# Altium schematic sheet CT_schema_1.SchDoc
size 546 x 556 mm
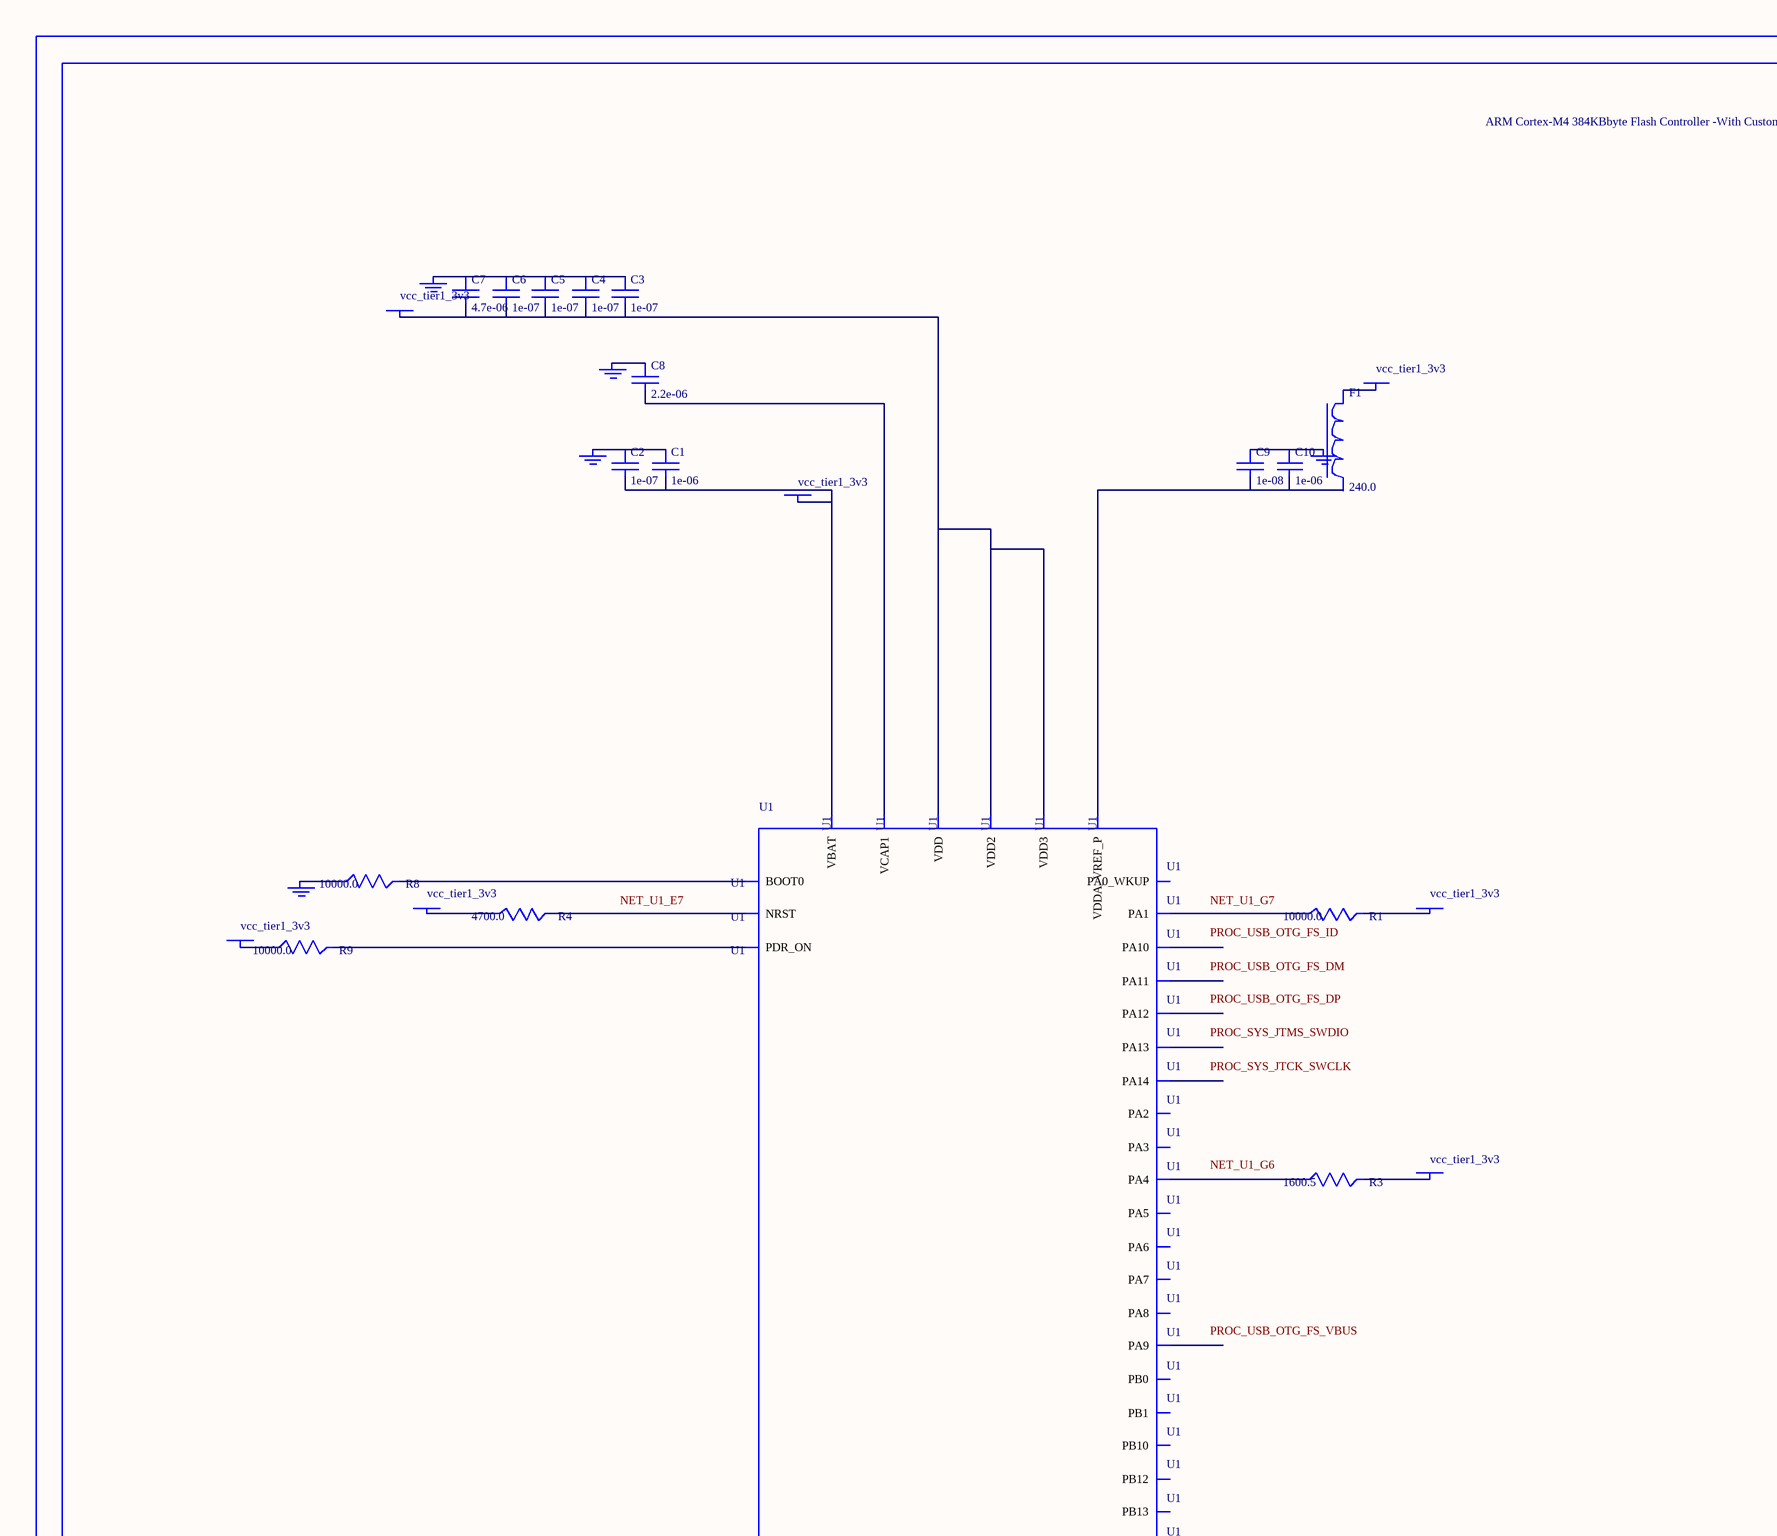
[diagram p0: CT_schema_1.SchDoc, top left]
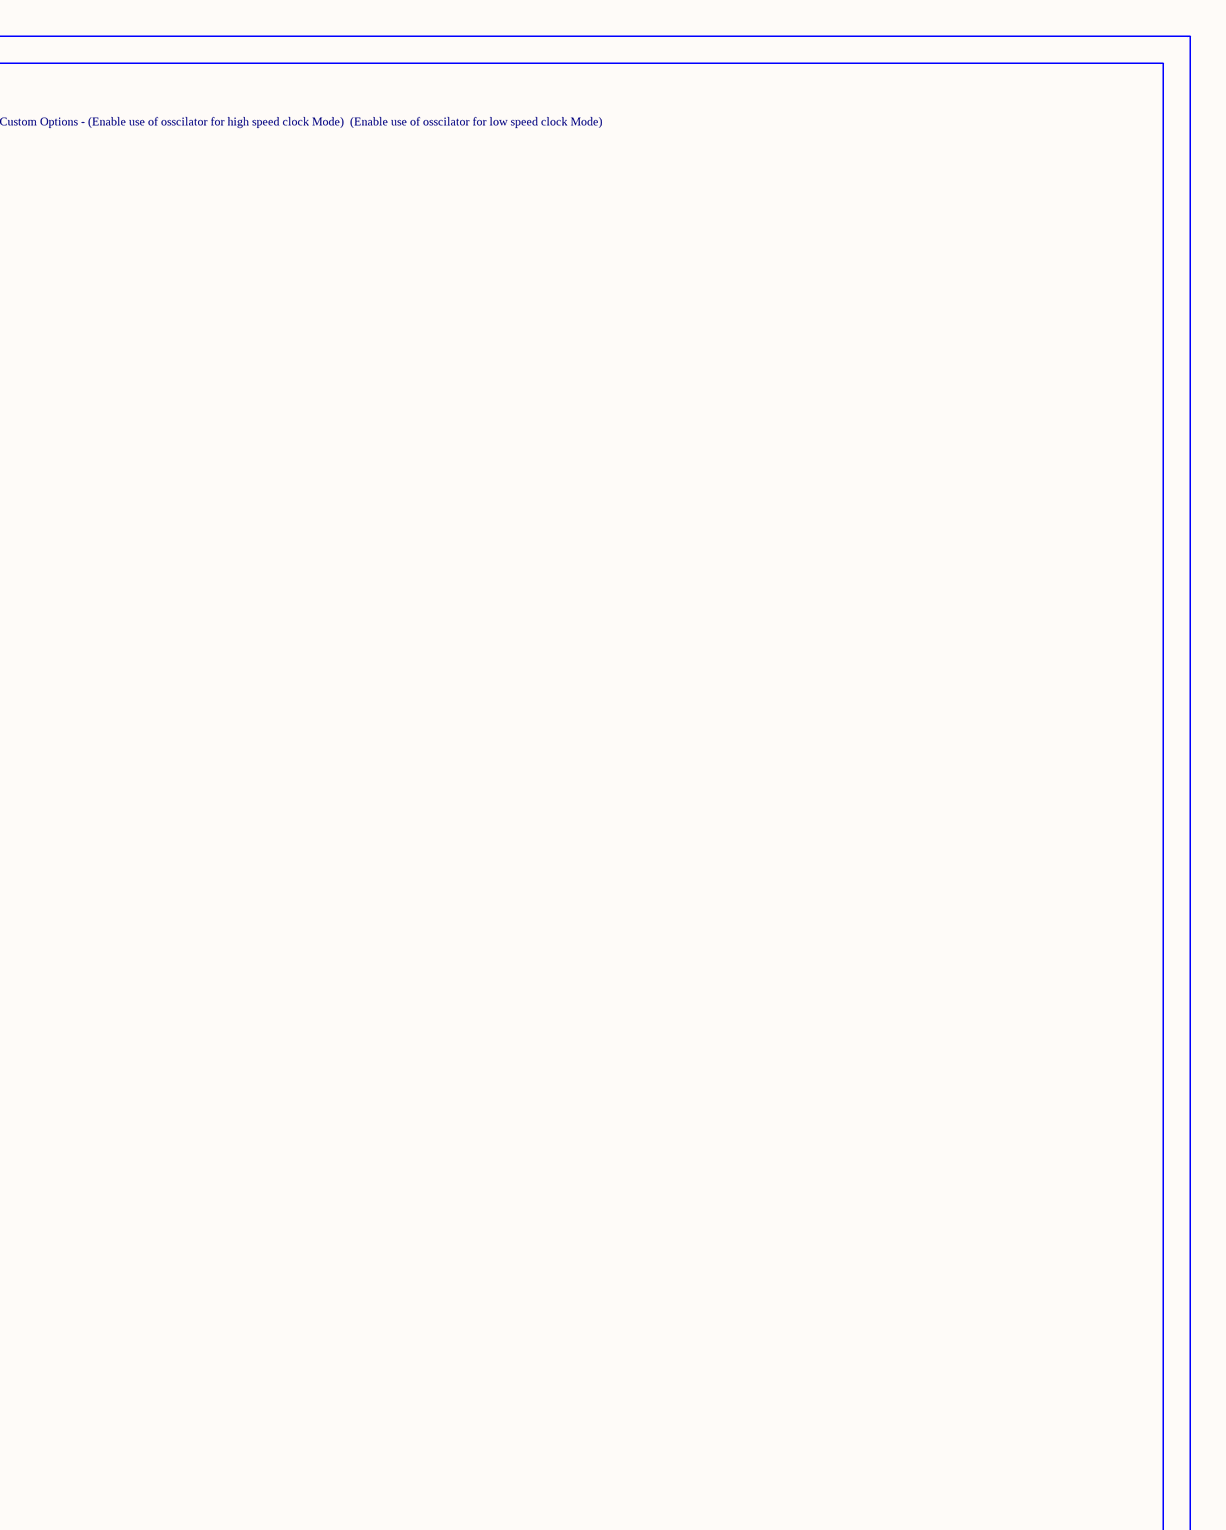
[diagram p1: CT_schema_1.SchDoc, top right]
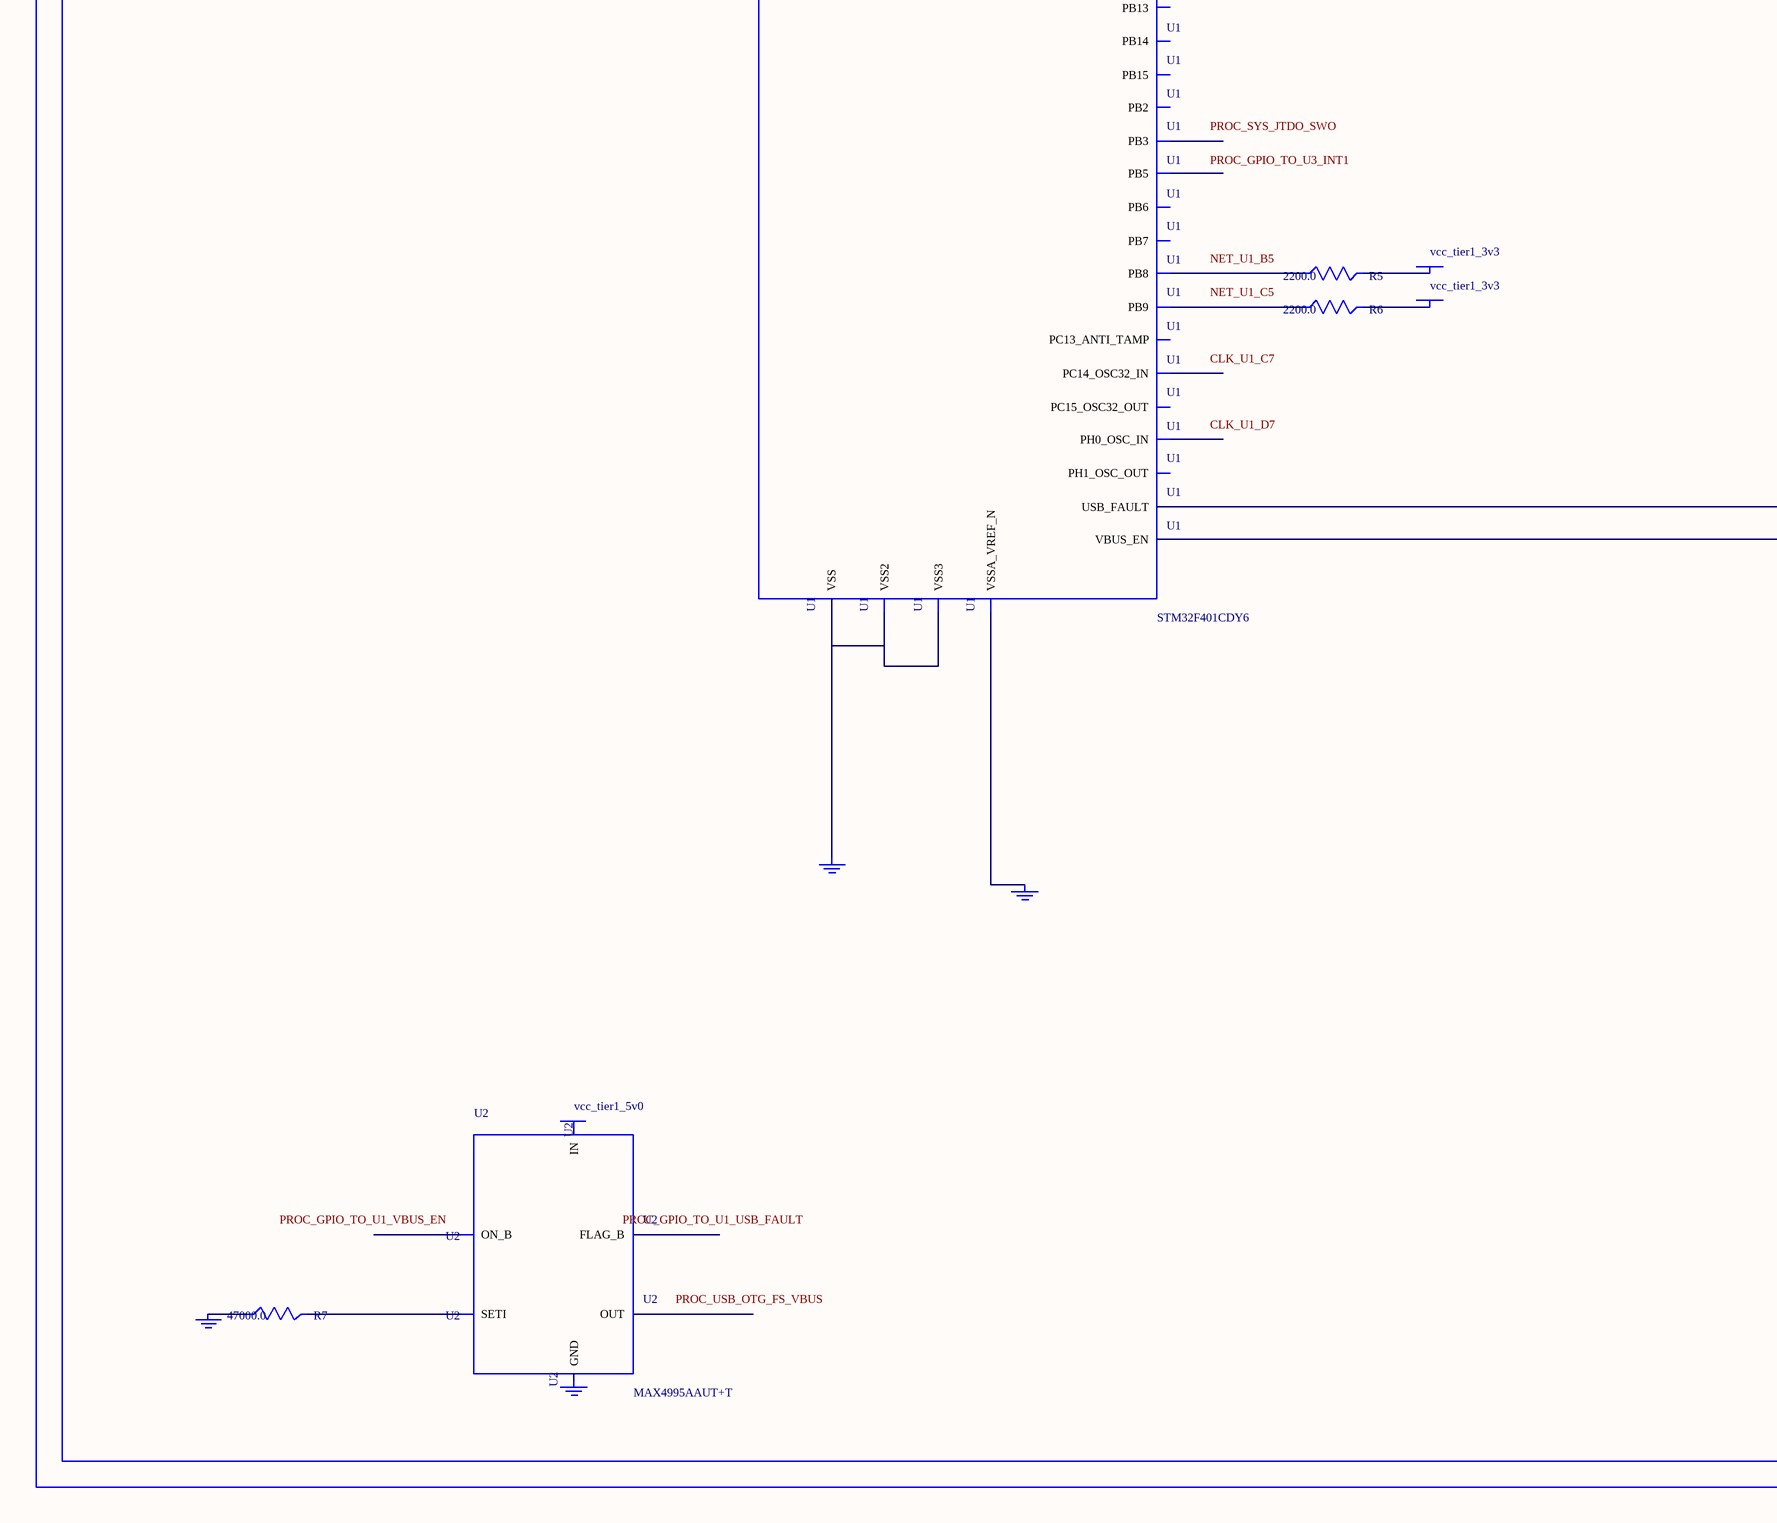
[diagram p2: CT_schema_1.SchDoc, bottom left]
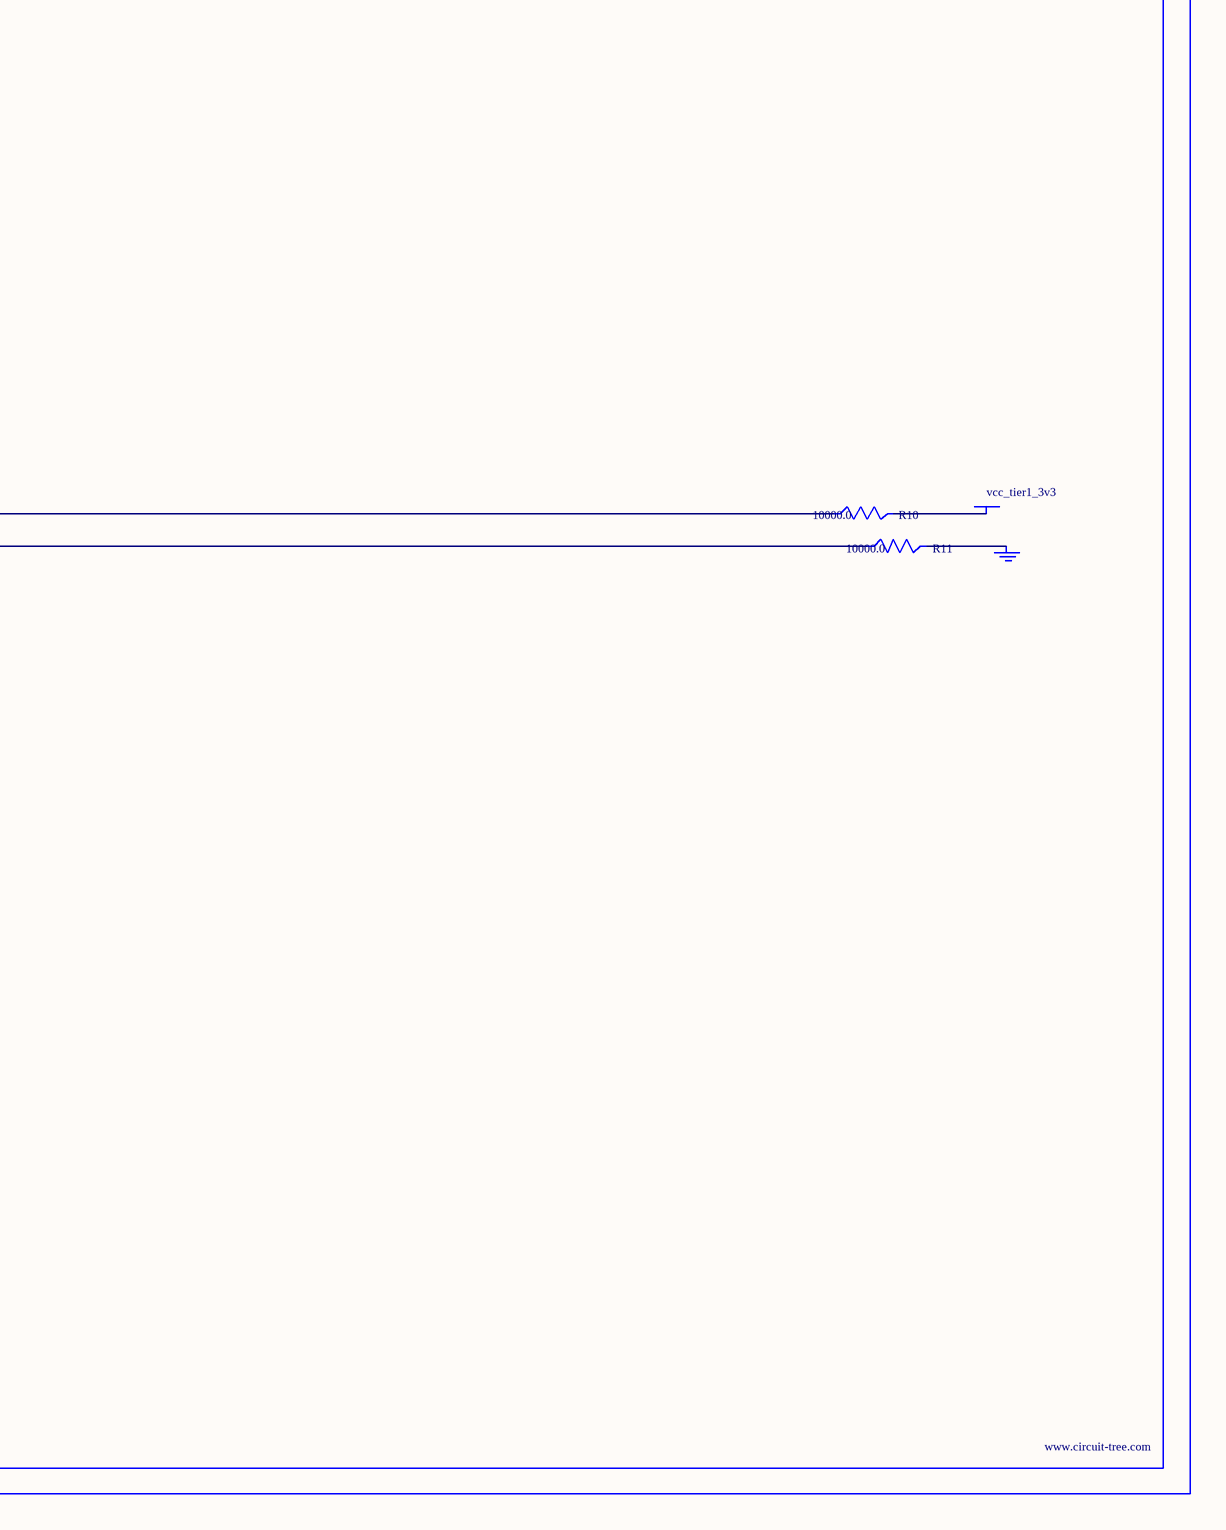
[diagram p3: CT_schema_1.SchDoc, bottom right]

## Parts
BORDER0  (no value)
C1  1e-06  [C0603]
C2  1e-07  [C0603]
C3  1e-07  [C0603]
C4  1e-07  [C0603]
C5  1e-07  [C0603]
C6  1e-07  [C0603]
C7  4.7e-06  [C0603]
C8  2.2e-06  [C0603]
C9  1e-08  [C0603]
C10  1e-06  [C0603]
F1  240.0  [L0603]
GND_INSTANCE_0_0  (no value)
GND_INSTANCE_0_1  (no value)
GND_INSTANCE_0_2  (no value)
GND_INSTANCE_0_3  (no value)
GND_INSTANCE_0_4  (no value)
GND_INSTANCE_0_5  (no value)
GND_INSTANCE_0_6  (no value)
GND_INSTANCE_0_7  (no value)
GND_INSTANCE_0_8  (no value)
GND_INSTANCE_0_9  (no value)
POWER_INSTANCE_0_0  vcc_tier1_3v3
POWER_INSTANCE_0_1  vcc_tier1_3v3
POWER_INSTANCE_0_2  vcc_tier1_3v3
POWER_INSTANCE_0_3  vcc_tier1_3v3
POWER_INSTANCE_0_4  vcc_tier1_3v3
POWER_INSTANCE_0_5  vcc_tier1_3v3
POWER_INSTANCE_0_6  vcc_tier1_3v3
POWER_INSTANCE_0_7  vcc_tier1_3v3
POWER_INSTANCE_0_8  vcc_tier1_3v3
POWER_INSTANCE_0_9  vcc_tier1_3v3
POWER_INSTANCE_0_10  vcc_tier1_5v0
R1  10000.0  [R0603]
R3  1600.5  [R0603]
R4  4700.0  [R0603]
R5  2200.0  [R0603]
R6  2200.0  [R0603]
R7  47000.0  [R0603]
R8  10000.0  [R0603]
R9  10000.0  [R0603]
R10  10000.0  [R0603]
R11  10000.0  [R0603]
U1  STM32F401CDY6  [WLCSP49]
U2  MAX4995AAUT+T  [SOT-23-6]

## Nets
NetC1_1: C1.1 C2.1 GND_INSTANCE_0_0.0(GND)
NetC1_2: C1.2 C2.2 POWER_INSTANCE_0_0.0(PWR) U1.B7(VBAT)
NetC3_1: C3.1 C4.1 C5.1 C6.1 C7.1 GND_INSTANCE_0_2.0(GND)
NetC3_2: C3.2 C4.2 C5.2 C6.2 C7.2 POWER_INSTANCE_0_2.0(PWR) U1.A7(VDD) U1.B2(VDD2) U1.F2(VDD3)
NetC8_1: C8.1 GND_INSTANCE_0_4.0(GND)
NetC8_2: C8.2 U1.G2(VCAP1)
NetC9_1: C9.1 C10.1 GND_INSTANCE_0_1.0(GND)
NetC9_2: C9.2 C10.2 U1.F7(VDDA_VREF_P)
NetF1_1: F1.1 POWER_INSTANCE_0_1.0(PWR)
NetGND_INSTANCE_0_3_0: GND_INSTANCE_0_3.0(GND) R8.1
NetGND_INSTANCE_0_5_0: GND_INSTANCE_0_5.0(GND) R11.2
NetGND_INSTANCE_0_6_0: GND_INSTANCE_0_6.0(GND) U1.E6(VSSA_VREF_N)
NetGND_INSTANCE_0_7_0: GND_INSTANCE_0_7.0(GND) U1.A6(VSS) U1.B1(VSS2) U1.D3(VSS3)
NetGND_INSTANCE_0_8_0: GND_INSTANCE_0_8.0(GND) R7.1
NetPOWER_INSTANCE_0_3_0: POWER_INSTANCE_0_3.0(PWR) R9.1
NetPOWER_INSTANCE_0_4_0: POWER_INSTANCE_0_4.0(PWR) R10.2
NetPOWER_INSTANCE_0_5_0: POWER_INSTANCE_0_5.0(PWR) R4.1
NetPOWER_INSTANCE_0_6_0: POWER_INSTANCE_0_6.0(PWR) R1.2
NetPOWER_INSTANCE_0_7_0: POWER_INSTANCE_0_7.0(PWR) R3.2
NetPOWER_INSTANCE_0_8_0: POWER_INSTANCE_0_8.0(PWR) R5.2
NetPOWER_INSTANCE_0_9_0: POWER_INSTANCE_0_9.0(PWR) R6.2
NetR1_1: R1.1 U1.G7(PA1)
NetR3_1: R3.1 U1.G6(PA4)
NetR4_2: R4.2 U1.E7(NRST)
NetR5_1: R5.1 U1.B5(PB8)
NetR6_1: R6.1 U1.C5(PB9)
NetR7_2: R7.2 U2.3(SETI)
NetR8_2: R8.2 U1.A5(BOOT0)
NetR9_2: R9.2 U1.B6(PDR_ON)
NetR10_1: R10.1 U1.A4(USB_FAULT)
NetR11_1: R11.1 U1.A2(VBUS_EN)

Not connected (* = marked no-connect by the designer): F1 2; GND_INSTANCE_0_9 0(GND); POWER_INSTANCE_0_10 0(PWR); U1 A1(PA14) A3(PB3) B3(PA13) B4(PB5) C1(PA11) C2(PA10) C3(PA12) C4(PB6) C6(PC15_OSC32_OUT) C7(PC14_OSC32_IN) D1(PA8) D2(PA9) D4(PB7) D5(PC13_ANTI_TAMP) D6(PH1_OSC_OUT) D7(PH0_OSC_IN) E1(PB15) E2(PB12) E3(PB10) E4(PA3) E5(PA2) F1(PB14) F3(PA7) F4(PA6) F5(PA5) F6(PA0_WKUP) G1(PB13) G3(PB2) G4(PB1) G5(PB0); U2 1(OUT) 2(GND) 4(ON_B) 5(IN) 6(FLAG_B)

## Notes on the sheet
- Labels drawn without touching a wire or pin: CLK_U1_C7, CLK_U1_D7, NET_U1_B5, NET_U1_C5, NET_U1_E7, NET_U1_G6, NET_U1_G7, PROC_GPIO_TO_U1_USB_FAULT, PROC_GPIO_TO_U1_VBUS_EN, PROC_GPIO_TO_U3_INT1, PROC_SYS_JTCK_SWCLK, PROC_SYS_JTDO_SWO, PROC_SYS_JTMS_SWDIO, PROC_USB_OTG_FS_DM, PROC_USB_OTG_FS_DP, PROC_USB_OTG_FS_ID, PROC_USB_OTG_FS_VBUS

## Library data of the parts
BORDER0 = BORDER_PAGE0
C1 C10 = C0603C105K3RACTU
C2-C6 = 06035C104K4Z2A
C7 = GRM188R6YA475KE15D
C8 = C0603C225K8RACTU
C9 = 06035C103K4Z2A
F1 = Z0603C241ASMST
GND_INSTANCE_0_0-GND_INSTANCE_0_9 = GND
POWER_INSTANCE_0_0-POWER_INSTANCE_0_10 = PWR
R1 R8-R11 = RC0603JR-0710KL
R3 = R3
R4 = RC0603JR-074K7L
R5 R6 = RC0603JR-072K2L
R7 = RC0603JR-0747KL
